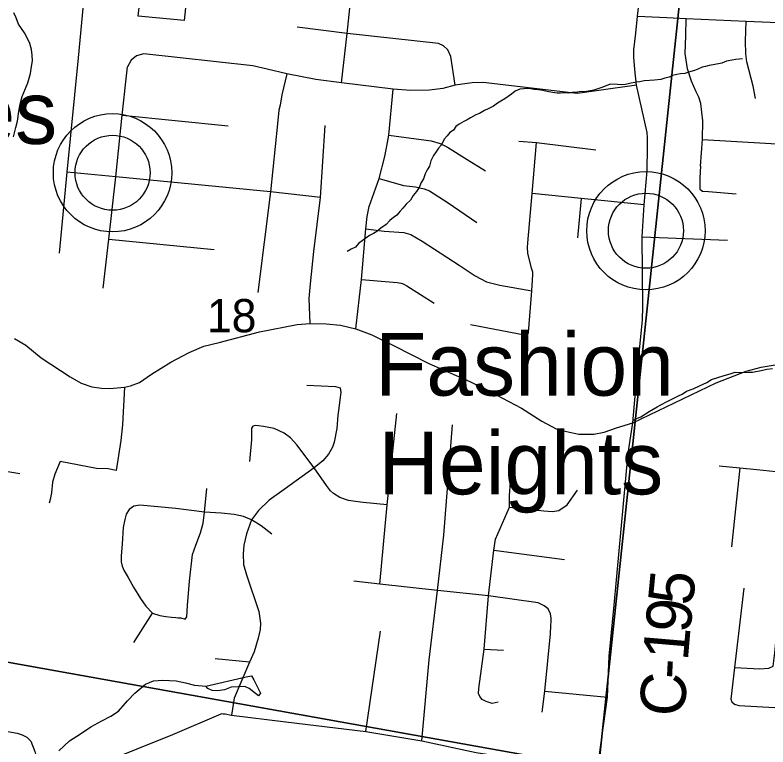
# Model space of a CAD drawing. Extents: x 0 to 34, y 0 to 22.
# Drawn here: x 6.917 to 7.863, y 16.255 to 17.176 of the extents above; entities that cross this region are included whole.
import ezdxf

# ---------------------------------------------------------------- set-up
doc = ezdxf.new("R2010")
doc.units = 0
for name, color, linetype in [('GM_X_City_Street', 7, 'Continuous'), ('GM_X_Corporation', 7, 'Continuous'), ('GM_X_County_Road', 7, 'Continuous'), ('GM_X_County_Road_Text', 7, 'Continuous'), ('GM_X_Minor_Lake', 7, 'Continuous'), ('GM_X_Minor_River', 7, 'Continuous'), ('GM_X_Section_Text', 7, 'Continuous'), ('GM_X_Township_Road', 7, 'Continuous'), ('GM_X_Unincorporated', 7, 'Continuous'), ('GM_X_Unincorporated_Location', 7, 'Continuous'), ('GM_X_Unincorporated_Text', 7, 'Continuous')]:
    doc.layers.add(name, color=color, linetype=linetype)

msp = doc.modelspace()

# ---------------------------------------------------------------- linework, layer by layer
at = {"layer": 'GM_X_City_Street'}
for points in [[(7.73626, 17.17253), (7.76063, 17.17119), (7.83577, 17.1679), (7.88622, 17.16596), (7.96008, 17.16299), (8.00847, 17.1604), (8.09018, 17.15677), (8.11414, 17.15549)], [(7.77863, 16.98562), (7.78106, 17.01919), (7.78137, 17.04261), (7.77909, 17.06447), (7.77635, 17.07216), (7.77304, 17.07892), (7.76723, 17.09244), (7.76235, 17.108), (7.75937, 17.12734), (7.76, 17.14958), (7.76063, 17.17119)], [(7.84777, 17.07081), (7.84486, 17.08609), (7.83671, 17.11696), (7.83561, 17.12687), (7.83498, 17.14259), (7.83577, 17.1679)], [(7.78106, 17.01919), (7.90336, 17.01207), (8.00934, 17.00696), (8.1949, 17.00064)]]:
    msp.add_lwpolyline(points, dxfattribs=at)
at = {"layer": 'GM_X_Corporation'}
for points in [[(7.75749, 17.24313), (7.65014, 16.22807), (6.62666, 16.41197), (6.72714, 17.3517)], [(7.75749, 17.24313), (8.74847, 17.19314), (8.6363, 16.19905), (7.65014, 16.22807)], [(7.65014, 16.22807), (7.54379, 15.20655), (6.51942, 15.39627), (6.62666, 16.41197)]]:
    msp.add_lwpolyline(points, close=True, dxfattribs=at)
at = {"layer": 'GM_X_County_Road'}
for points in [[(7.69325, 16.6628), (7.69899, 16.72501), (7.70539, 16.79178), (7.70605, 16.8089), (7.70507, 16.89642), (7.70788, 16.9367), (7.71154, 16.97968), (7.71187, 17.00938), (7.71193, 17.02124), (7.71128, 17.02803), (7.69808, 17.08723), (7.69612, 17.10722), (7.69454, 17.12257), (7.69459, 17.13179), (7.69716, 17.15269), (7.69923, 17.17425), (7.702, 17.19542), (7.70331, 17.21685), (7.70697, 17.24639)], [(6.91604, 16.76887), (6.93026, 16.76022), (6.94963, 16.74425), (6.98628, 16.72031), (7.00013, 16.71242), (7.01331, 16.70797), (7.02541, 16.70619), (7.03602, 16.70596), (7.05445, 16.70745), (7.06188, 16.70919), (7.07336, 16.71349), (7.08837, 16.72378), (7.1126, 16.73881), (7.13563, 16.7512), (7.15439, 16.75913), (7.17345, 16.76365), (7.22418, 16.77702), (7.27172, 16.78651), (7.28795, 16.78761), (7.30777, 16.78706), (7.3258, 16.78532), (7.34544, 16.78068), (7.36548, 16.77346), (7.39279, 16.7601), (7.43714, 16.73741), (7.48837, 16.71453), (7.52179, 16.69772), (7.55343, 16.68099), (7.57917, 16.66473), (7.59712, 16.65514), (7.60993, 16.65176), (7.62577, 16.64829), (7.64437, 16.64855), (7.65733, 16.65086), (7.67302, 16.65613), (7.69325, 16.6628), (7.79836, 16.71289), (7.83608, 16.72751), (7.85463, 16.73254), (7.87491, 16.73615)], [(7.58249, 15.60554), (7.58756, 15.65519), (7.59384, 15.71425), (7.5992, 15.76457), (7.61792, 15.94058), (7.62113, 15.9725), (7.63242, 16.08483), (7.63341, 16.09465), (7.64876, 16.22425), (7.66156, 16.31739), (7.66386, 16.36903), (7.67012, 16.43339), (7.68774, 16.62461), (7.69325, 16.6628)], [(6.90828, 16.17397), (6.92096, 16.18179), (6.93139, 16.19111), (6.94814, 16.20005), (7.02566, 16.23437), (7.1152, 16.27036), (7.17607, 16.29634), (7.17739, 16.29676), (7.17871, 16.29675), (7.18117, 16.29642), (7.18894, 16.29492), (7.25726, 16.28661), (7.35784, 16.27415), (7.42833, 16.26276), (7.49667, 16.24808), (7.64876, 16.22425), (7.66742, 16.22242), (7.66839, 16.22239)]]:
    msp.add_lwpolyline(points, dxfattribs=at)
at = {"layer": 'GM_X_Minor_Lake'}
for points in [[(7.15655, 16.33128), (7.20747, 16.3429), (7.21396, 16.34425), (7.21686, 16.33923), (7.22553, 16.32268), (7.22278, 16.31933), (7.21906, 16.32209), (7.21125, 16.32837), (7.20563, 16.3308), (7.19689, 16.33065), (7.18853, 16.33011), (7.18009, 16.32692)], [(7.18009, 16.32692), (7.17132, 16.32563), (7.1645, 16.32582), (7.15925, 16.32823), (7.15655, 16.33128)]]:
    msp.add_lwpolyline(points, dxfattribs=at)
at = {"layer": 'GM_X_Minor_River'}
for points in [[(6.91477, 17.02236), (6.91804, 17.03408), (6.9201, 17.04203), (6.92184, 17.05416), (6.92312, 17.06136), (6.92399, 17.06705), (6.92601, 17.07309), (6.93001, 17.08328), (6.93282, 17.09046), (6.93647, 17.10218), (6.93777, 17.1109), (6.93867, 17.1181), (6.93842, 17.12533), (6.9374, 17.13219), (6.93563, 17.13982), (6.93194, 17.14711), (6.92862, 17.15325), (6.92117, 17.16403), (6.91827, 17.17206), (6.91532, 17.1782)], [(7.83149, 17.12051), (7.8231, 17.1196), (7.81814, 17.11898), (7.81126, 17.11765), (7.80549, 17.11515), (7.7944, 17.11317), (7.78943, 17.11217), (7.78483, 17.11077), (7.78063, 17.11013), (7.77524, 17.10761), (7.77101, 17.10583), (7.76642, 17.10481), (7.75873, 17.10198), (7.7534, 17.10175), (7.74881, 17.10073), (7.74346, 17.09974), (7.73922, 17.09757), (7.73386, 17.0962), (7.72849, 17.09444), (7.72047, 17.09352), (7.71439, 17.09331), (7.70752, 17.09274), (7.70217, 17.09175), (7.69797, 17.09111), (7.68918, 17.08945), (7.68421, 17.08844), (7.67925, 17.08782), (7.67432, 17.08834), (7.66482, 17.08861), (7.6556, 17.08505), (7.64945, 17.08294), (7.64446, 17.08118), (7.63987, 17.08016), (7.633, 17.07921), (7.62844, 17.07934), (7.62157, 17.07839), (7.61738, 17.07812), (7.61318, 17.07748), (7.60786, 17.07763), (7.60253, 17.0774), (7.59835, 17.07751), (7.59228, 17.07806), (7.58585, 17.07939), (7.58018, 17.08069), (7.57488, 17.0816), (7.56957, 17.08213), (7.56541, 17.083), (7.56123, 17.08312), (7.55628, 17.08288), (7.55132, 17.08226), (7.54555, 17.07975), (7.54089, 17.07607), (7.53274, 17.07021), (7.52772, 17.0673), (7.52346, 17.06475), (7.51842, 17.06108), (7.51148, 17.05747), (7.50687, 17.05569), (7.50067, 17.05168), (7.49606, 17.0499), (7.4895, 17.04628), (7.48525, 17.04373), (7.481, 17.04156), (7.47521, 17.0383), (7.47095, 17.03537), (7.46816, 17.03088), (7.46352, 17.02796), (7.45999, 17.02387), (7.45645, 17.0194), (7.45283, 17.01226), (7.4493, 17.00817), (7.44574, 17.00332), (7.44296, 16.99882), (7.43973, 16.99206), (7.43766, 16.98564), (7.43486, 16.98077), (7.43245, 16.97588), (7.43037, 16.96947), (7.42721, 16.96498), (7.42475, 16.95858), (7.42158, 16.95372), (7.41725, 16.9485), (7.41406, 16.94288), (7.4086, 16.9377), (7.40428, 16.93287), (7.40074, 16.9284), (7.39681, 16.92394), (7.39255, 16.92101), (7.38789, 16.91733), (7.38318, 16.91213), (7.37659, 16.90736), (7.37153, 16.90332), (7.36728, 16.90077), (7.36227, 16.89824), (7.3549, 16.89273), (7.34869, 16.88834), (7.34476, 16.8835), (7.33936, 16.88098), (7.33434, 16.87807)], [(7.69365, 16.6654), (7.69829, 16.66794), (7.70367, 16.67008), (7.71412, 16.67702), (7.72417, 16.68283), (7.7288, 16.68537), (7.73652, 16.68935), (7.74346, 16.69296), (7.75078, 16.69656), (7.7554, 16.69872), (7.76083, 16.70238), (7.76928, 16.70557), (7.77736, 16.70915), (7.78661, 16.71347), (7.79241, 16.71711), (7.80161, 16.7199), (7.81121, 16.72306), (7.81581, 16.72446), (7.82195, 16.72657), (7.83068, 16.72594), (7.8383, 16.72649), (7.844, 16.72633), (7.8547, 16.72832), (7.86197, 16.73002), (7.86884, 16.73097)], [(6.97193, 16.25007), (6.98515, 16.26265), (6.99904, 16.27142), (7.01217, 16.28021), (7.02602, 16.28783), (7.03718, 16.29363), (7.04682, 16.29985), (7.05816, 16.31285), (7.06751, 16.3225), (7.08071, 16.33394), (7.09107, 16.33824), (7.10285, 16.33908), (7.11952, 16.3379), (7.13123, 16.33571), (7.14254, 16.33277), (7.15655, 16.33128)]]:
    msp.add_lwpolyline(points, dxfattribs=at)
at = {"layer": 'GM_X_Township_Road'}
for p, q in [((7.69923, 17.17425), (7.73626, 17.17253)), ((7.05146, 17.04956), (7.18489, 17.0363)), ((7.62862, 16.94472), (7.62401, 16.89545)), ((7.03488, 16.89384), (7.16721, 16.88085)), ((7.70507, 16.89642), (7.81257, 16.8923)), ((7.82809, 16.60587), (7.81726, 16.50662)), ((7.51869, 16.50261), (7.60747, 16.49069)), ((7.06617, 16.38634), (7.08955, 16.42321)), ((7.35784, 16.27415), (7.37623, 16.40037)), ((7.5065, 16.37789), (7.53079, 16.37673)), ((7.21167, 16.36135), (7.1686, 16.36567)), ((7.58274, 16.32522), (7.66156, 16.31739))]:
    msp.add_line(p, q, dxfattribs=at)
for points in [[(7.01941, 17.32214), (7.00508, 17.21333), (7.00263, 17.18835), (6.99624, 17.12174), (6.98211, 16.9781), (6.97254, 16.87606)], [(7.14594, 17.30851), (7.14115, 17.27554), (7.13544, 17.23355), (7.13305, 17.20464), (7.12968, 17.16865), (7.0718, 17.1742), (7.08572, 17.29876)], [(7.32745, 17.09054), (7.33417, 17.15233), (7.3408, 17.21255), (7.34909, 17.28622)], [(7.47009, 17.0875), (7.46475, 17.1236), (7.46106, 17.1317), (7.45535, 17.13686), (7.44928, 17.13999), (7.33417, 17.15233), (7.27155, 17.16025)], [(7.69808, 17.08723), (7.65078, 17.08089), (7.63258, 17.07826), (7.62358, 17.07695), (7.61602, 17.07771), (7.50516, 17.09072), (7.49146, 17.09045), (7.47009, 17.0875), (7.45454, 17.0834), (7.43776, 17.08115), (7.41423, 17.08065), (7.39237, 17.08253), (7.32745, 17.09054), (7.29485, 17.09469), (7.25838, 17.10178), (7.23361, 17.10757), (7.21565, 17.11172), (7.07899, 17.12673), (7.06942, 17.12434), (7.06279, 17.11881), (7.05818, 17.11061)], [(7.0278, 16.83205), (7.03488, 16.89384), (7.04379, 16.97222), (7.05146, 17.04956), (7.05818, 17.11061)], [(7.25838, 17.10178), (7.2523, 17.07516), (7.25009, 17.06236), (7.24853, 17.0561), (7.24669, 17.03888), (7.23794, 16.95324), (7.22224, 16.82668)], [(7.34544, 16.78068), (7.35239, 16.84298), (7.35796, 16.90652), (7.35933, 16.92226), (7.36185, 16.93459), (7.37446, 16.9698), (7.38181, 16.99776), (7.38488, 17.01542), (7.38665, 17.02471), (7.39237, 17.08253)], [(7.28795, 16.78761), (7.28656, 16.81896), (7.28832, 16.83764), (7.29237, 16.87799), (7.30082, 16.94595), (7.30683, 17.03647)], [(7.38665, 17.02471), (7.44003, 17.01736), (7.45113, 17.01384), (7.46029, 17.00943), (7.48531, 16.99392), (7.50839, 16.97948)], [(7.55024, 17.01701), (7.57227, 17.01513), (7.64695, 17.00606)], [(7.48947, 16.78634), (7.55741, 16.77351), (7.55919, 16.77364), (7.56084, 16.77417), (7.56185, 16.77519), (7.56242, 16.7764), (7.56628, 16.82876), (7.56777, 16.84914), (7.56779, 16.85112), (7.56772, 16.8523), (7.56751, 16.85332), (7.566, 16.85704), (7.56162, 16.87624), (7.56118, 16.88305), (7.56151, 16.88907), (7.56688, 16.95115), (7.57227, 17.01513)], [(7.30082, 16.94595), (7.23794, 16.95324), (7.04379, 16.97222), (6.98211, 16.9781)], [(7.77863, 16.98562), (7.77768, 16.97093), (7.77752, 16.96432), (7.77784, 16.95639), (7.78114, 16.95426), (7.78853, 16.95355), (7.82314, 16.95083)], [(7.37446, 16.9698), (7.40514, 16.96107), (7.42012, 16.95948), (7.43131, 16.95719), (7.43765, 16.95463), (7.46135, 16.93922), (7.49745, 16.91481)], [(7.70788, 16.9367), (7.62862, 16.94472), (7.56688, 16.95115)], [(7.35796, 16.90652), (7.38107, 16.90389), (7.40578, 16.90202), (7.41422, 16.89949), (7.42848, 16.89127), (7.47531, 16.86089), (7.49505, 16.84762), (7.50931, 16.83984), (7.5263, 16.836), (7.56628, 16.82876)], [(7.35239, 16.84298), (7.39725, 16.83906), (7.40231, 16.83825), (7.40495, 16.83744), (7.4094, 16.83501), (7.44382, 16.81314)], [(7.05445, 16.70745), (7.05182, 16.66016), (7.04968, 16.64059), (7.04399, 16.60251), (7.03402, 16.60465), (7.01943, 16.60536), (6.97353, 16.6139), (6.96703, 16.59793), (6.96413, 16.58778), (6.96268, 16.57472), (6.96123, 16.56601), (6.95994, 16.56172)], [(7.28373, 16.71011), (7.31973, 16.70829), (7.32549, 16.70677), (7.32626, 16.7007), (7.32512, 16.69163), (7.32383, 16.68126), (7.32261, 16.6723), (7.32155, 16.65559), (7.31813, 16.63812), (7.31593, 16.6322), (7.31092, 16.62339), (7.30393, 16.61466), (7.29269, 16.60615), (7.25533, 16.57881), (7.2365, 16.56545), (7.22297, 16.55254), (7.21399, 16.54065), (7.20786, 16.52297), (7.20454, 16.50854), (7.20364, 16.49788), (7.2041, 16.48461), (7.20798, 16.47125), (7.22329, 16.4254), (7.22535, 16.41048), (7.22506, 16.4026), (7.22254, 16.39166), (7.21762, 16.3747), (7.21167, 16.36135), (7.19243, 16.31608), (7.18894, 16.29492)], [(6.65201, 16.68031), (6.73099, 16.66701), (6.72532, 16.6392), (6.72478, 16.63438), (6.73048, 16.6334), (6.82658, 16.6171), (6.90281, 16.60211), (6.92292, 16.59883)], [(7.37528, 16.45964), (7.38454, 16.55928), (7.39681, 16.67422)], [(7.34471, 16.56365), (7.3359, 16.56476), (7.32512, 16.56863), (7.31714, 16.57365), (7.31327, 16.57722), (7.30849, 16.5836), (7.29269, 16.60615), (7.27097, 16.63478), (7.26323, 16.64374), (7.25533, 16.64967), (7.24242, 16.65559), (7.22928, 16.65809), (7.22306, 16.65878), (7.21858, 16.65931), (7.21569, 16.65832), (7.21394, 16.65604), (7.21409, 16.65149), (7.21403, 16.64121), (7.21151, 16.61398)], [(7.42833, 16.26276), (7.43725, 16.36451), (7.44804, 16.4518), (7.45606, 16.52111), (7.46676, 16.66017)], [(7.52412, 16.31108), (7.51647, 16.30965), (7.50917, 16.31196), (7.50419, 16.31472), (7.50116, 16.31828), (7.49956, 16.32211), (7.49983, 16.32824), (7.5065, 16.37789), (7.5121, 16.44487), (7.51869, 16.50261), (7.52065, 16.51622), (7.53826, 16.55643), (7.53844, 16.57102), (7.54111, 16.60465)], [(7.80181, 16.60844), (7.82809, 16.60587), (7.84928, 16.60382)], [(7.84928, 16.60382), (7.88107, 16.60074), (7.92956, 16.59436), (7.97476, 16.58838), (7.99966, 16.58509)], [(7.12186, 16.41734), (7.12543, 16.41712), (7.13056, 16.41576), (7.13282, 16.4187), (7.13344, 16.42564), (7.13356, 16.43266), (7.13632, 16.46326), (7.1399, 16.497), (7.144, 16.50885), (7.14982, 16.52438), (7.15355, 16.53624), (7.1549, 16.55031), (7.15795, 16.57991)], [(7.53826, 16.55643), (7.58167, 16.55198), (7.59253, 16.55091), (7.60053, 16.55234), (7.61085, 16.55946), (7.62384, 16.57778)], [(7.38454, 16.55928), (7.35451, 16.56241), (7.34471, 16.56365)], [(7.23963, 16.52263), (7.22619, 16.53325), (7.21399, 16.54065), (7.20405, 16.54472), (7.19224, 16.54731), (7.17592, 16.54907), (7.1549, 16.55031), (7.11881, 16.55471), (7.07362, 16.55923), (7.06628, 16.55799), (7.06041, 16.55347), (7.05668, 16.54771), (7.05478, 16.54095), (7.05295, 16.53076), (7.05148, 16.51009), (7.05023, 16.49552), (7.05035, 16.48773), (7.05159, 16.48219), (7.05419, 16.47631), (7.05916, 16.46795), (7.06594, 16.45587), (7.07475, 16.44163), (7.0813, 16.4318), (7.08955, 16.42321), (7.09899, 16.42023), (7.10638, 16.41898), (7.11367, 16.41808), (7.11921, 16.41762), (7.12186, 16.41734)], [(7.57931, 16.29879), (7.58274, 16.32522), (7.59004, 16.39737), (7.59039, 16.40715), (7.59075, 16.41302), (7.59075, 16.41694), (7.59004, 16.42245), (7.58684, 16.4285), (7.58185, 16.4326), (7.57438, 16.43615), (7.5121, 16.44487), (7.44804, 16.4518), (7.37528, 16.45964), (7.34254, 16.46355)], [(7.83289, 16.45476), (7.82142, 16.35468), (7.81682, 16.31519), (7.81787, 16.31175), (7.8212, 16.30862), (7.82647, 16.30696), (7.89446, 16.30323), (7.90044, 16.30291)], [(7.82142, 16.35468), (7.85296, 16.35313), (7.86443, 16.35391), (7.86963, 16.35652), (7.87068, 16.36329), (7.87198, 16.37319), (7.87928, 16.45164)], [(6.85221, 16.2841), (6.85813, 16.28257), (6.86318, 16.28147), (6.87239, 16.28059), (6.89213, 16.27708), (6.90792, 16.27445), (6.91954, 16.27226), (6.92568, 16.27029), (6.93183, 16.26722), (6.93665, 16.26217), (6.94191, 16.24901), (6.94433, 16.23914), (6.94586, 16.23059), (6.94389, 16.22291), (6.94257, 16.21655), (6.94323, 16.20822), (6.94564, 16.20449), (6.94814, 16.20005)]]:
    msp.add_lwpolyline(points, dxfattribs=at)
at = {"layer": 'GM_X_Unincorporated'}
for centre, radius in [((7.03944, 16.97718), 0.0744), ((7.03944, 16.97718), 0.04716), ((7.70988, 16.9043), 0.0744), ((7.70988, 16.9043), 0.04716)]:
    msp.add_circle(centre, radius, dxfattribs=at)
at = {"layer": 'GM_X_Unincorporated_Location'}
for p, q in [((7.03944, 16.97718), (7.03944, 16.97718)), ((7.70988, 16.9043), (7.70988, 16.9043))]:
    msp.add_line(p, q, dxfattribs=at)

# ---------------------------------------------------------------- texts
at = {"layer": 'GM_X_County_Road_Text'}
for s, rotation, p in [('5', 84.46752, (7.76874, 16.43174)), ('9', 84.58507, (7.76544, 16.39693)), ('1', 85.13112, (7.76248, 16.3622)), ('-', 87.04482, (7.76132, 16.3394)), ('C', 86.46164, (7.7584, 16.29219))]:
    msp.add_text(s, height=0.05682, rotation=rotation, dxfattribs=at).set_placement(p)
at = {"layer": 'GM_X_Section_Text'}
msp.add_text('18', height=0.041856, rotation=0.00001, dxfattribs=at).set_placement((7.15809, 16.77652))
at = {"layer": 'GM_X_Unincorporated_Text'}
for s, p in [('The Pines', (6.49434, 17.0135)), ('Fashion', (7.36934, 16.69683)), ('Heights', (7.3735, 16.57267))]:
    msp.add_text(s, height=0.078977, rotation=0.00001, dxfattribs=at).set_placement(p)

doc.saveas('drawing.dxf')
